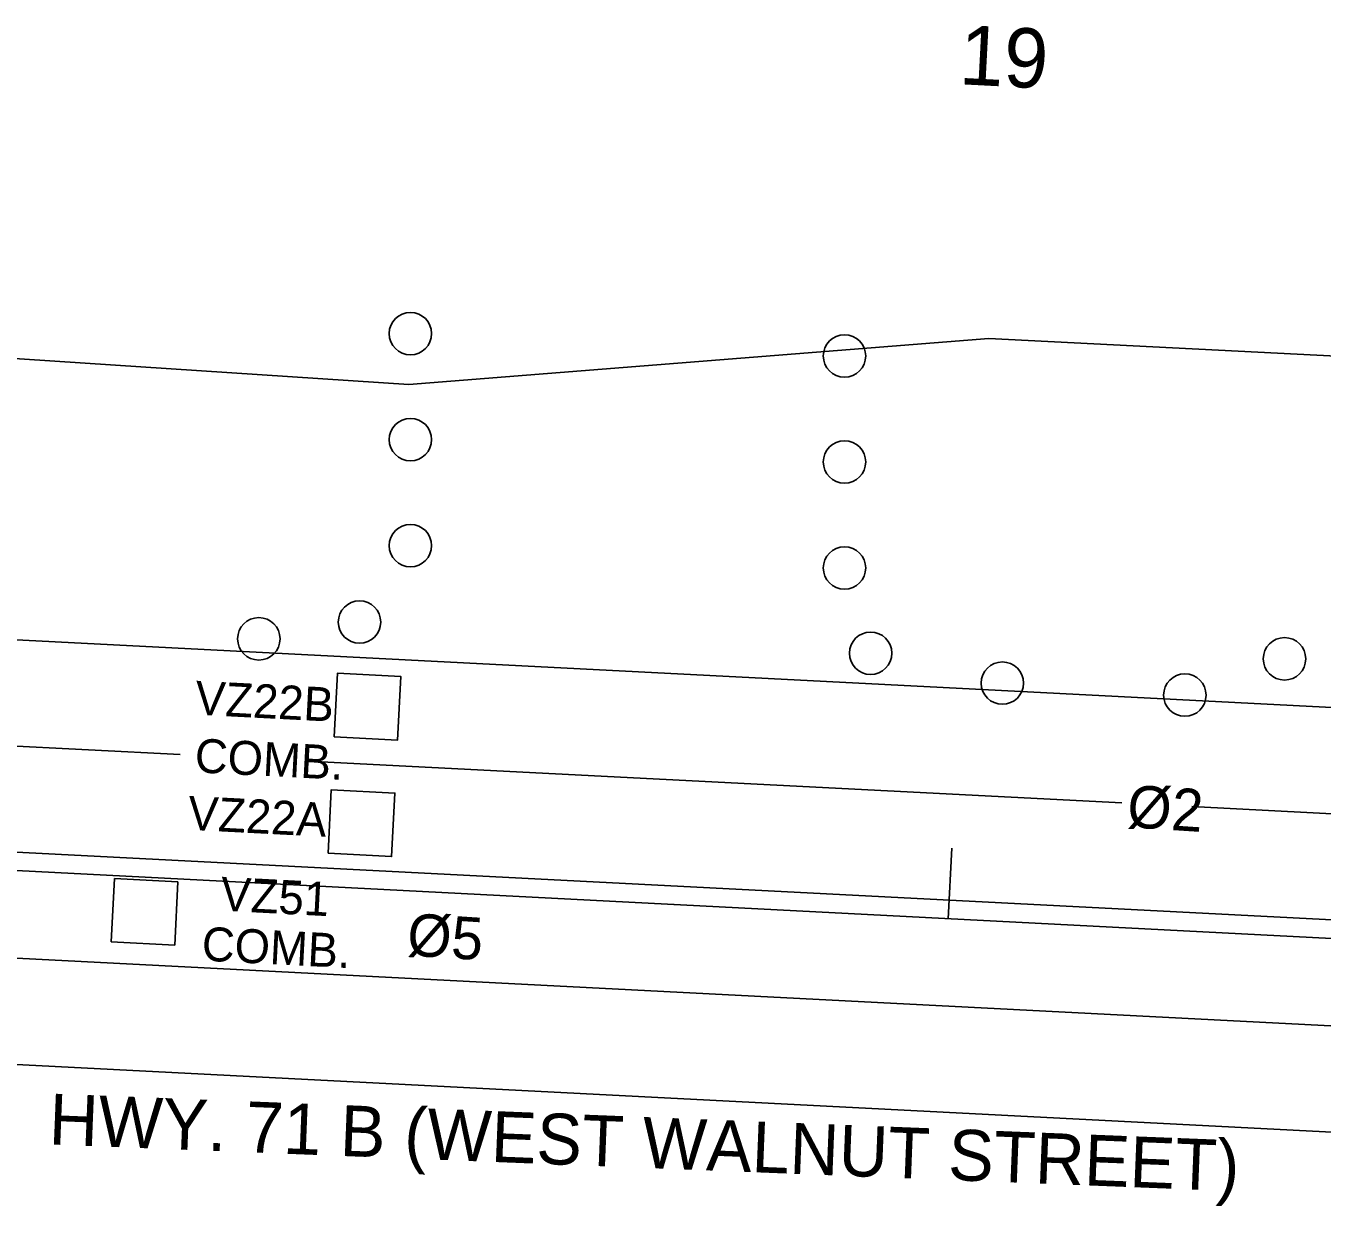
# Model space of a CAD drawing. Extents: x 679444 to 687671, y 733868 to 736107.
# Drawn here: x 681092.3 to 681214.5, y 735100.5 to 735212.9 of the extents above; entities that cross this region are included whole.
import ezdxf

# ---------------------------------------------------------------- set-up
doc = ezdxf.new("R2010")
doc.units = 0
for name, color, linetype in [('$', 7, 'Continuous'), ('MOT Stage 1', 7, 'Continuous'), ('MOT Stage 1 Lanes', 7, 'Continuous'), ('R_Horz Alg Station', 7, 'Continuous'), ('RW-EX', 7, 'Continuous'), ('TITEXT', 7, 'Continuous'), ('Video-Zones-pr', 7, 'Continuous')]:
    doc.layers.add(name, color=color, linetype=linetype)

# ---------------------------------------------------------------- blocks, each defined once
blk = doc.blocks.new('BAREL_1498')
at = {"layer": 'MOT Stage 1'}
blk.add_circle((0, 0.01), 2.88, dxfattribs=at)
blk = doc.blocks.new('BAREL_1499')
at = {"layer": 'MOT Stage 1'}
blk.add_circle((0, 0.01), 2.88, dxfattribs=at)
blk = doc.blocks.new('BAREL_1500')
at = {"layer": 'MOT Stage 1'}
blk.add_circle((0, 0.01), 2.88, dxfattribs=at)
blk = doc.blocks.new('BAREL_1501')
at = {"layer": 'MOT Stage 1'}
blk.add_circle((0, 0.01), 2.88, dxfattribs=at)
blk = doc.blocks.new('BAREL_1502')
at = {"layer": 'MOT Stage 1'}
blk.add_circle((0, 0.01), 2.88, dxfattribs=at)
blk = doc.blocks.new('BAREL_1504')
at = {"layer": 'MOT Stage 1'}
blk.add_circle((0, 0.01), 2.88, dxfattribs=at)
blk = doc.blocks.new('BAREL_1505')
at = {"layer": 'MOT Stage 1'}
blk.add_circle((0, 0.01), 2.88, dxfattribs=at)
blk = doc.blocks.new('BAREL_1506')
at = {"layer": 'MOT Stage 1'}
blk.add_circle((0, 0.01), 2.88, dxfattribs=at)
blk = doc.blocks.new('BAREL_1507')
at = {"layer": 'MOT Stage 1'}
blk.add_circle((0, 0.01), 2.88, dxfattribs=at)
blk = doc.blocks.new('BAREL_1525')
at = {"layer": 'MOT Stage 1'}
blk.add_circle((0, 0.01), 2.88, dxfattribs=at)
blk = doc.blocks.new('BAREL_1541')
at = {"layer": 'MOT Stage 1'}
blk.add_circle((0, 0.01), 2.88, dxfattribs=at)
blk = doc.blocks.new('BAREL_1542')
at = {"layer": 'MOT Stage 1'}
blk.add_circle((0, 0.01), 2.88, dxfattribs=at)

msp = doc.modelspace()

# ---------------------------------------------------------------- linework, layer by layer
at = {"layer": 'MOT Stage 1 Lanes'}
for p, q in [((681043.86, 735157.43), (681230.33, 735147.83)), ((681043.34, 735147.44), (681106.86, 735144.17)), ((681120.16, 735143.49), (681195.65, 735139.6)), ((681202.27, 735139.26), (681229.82, 735137.84)), ((681042.83, 735137.46), (681229.3, 735127.86)), ((681041.8, 735117.48), (681228.28, 735107.88))]:
    msp.add_line(p, q, dxfattribs=at)
msp.add_lwpolyline([(681042.86, 735157.48), (681041.31, 735127.52), (681228.79, 735117.87)], dxfattribs=at)
at = {"layer": 'R_Horz Alg Station'}
msp.add_line((680979.55, 735139), (682304.99, 735070.5), dxfattribs=at)
msp.add_lwpolyline([(681179.63, 735135.34), (681179.28, 735128.68)], dxfattribs=at)
at = {"layer": 'RW-EX'}
msp.add_lwpolyline([(681053.04, 735199.88), (681077.83, 735182.39), (681128.41, 735179.07), (681183.11, 735183.4), (681262.95, 735179.36), (681262.33, 735164.44), (681417.02, 735156.45)], dxfattribs=at)
at = {"layer": 'Video-Zones-pr'}
for points in [[(681121.36, 735145.84), (681121.67, 735151.83), (681127.66, 735151.52), (681127.35, 735145.53)], [(681120.79, 735134.85), (681121.1, 735140.84), (681127.1, 735140.53), (681126.79, 735134.54)]]:
    msp.add_lwpolyline(points, close=True, dxfattribs=at)
for points in [[(681100.64, 735132.48), (681100.33, 735126.49)], [(681100.64, 735132.48), (681106.64, 735132.17)], [(681106.64, 735132.17), (681106.33, 735126.18)], [(681100.33, 735126.49), (681106.33, 735126.18)]]:
    msp.add_lwpolyline(points, dxfattribs=at)

# ---------------------------------------------------------------- block references
at = {"layer": 'MOT Stage 1', "xscale": 0.6945420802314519, "yscale": 0.6945420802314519, "rotation": 87.04179557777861}
for name, p in [('BAREL_1498', (681128.57, 735183.87)), ('BAREL_1504', (681169.51, 735181.76)), ('BAREL_1499', (681128.57, 735173.87)), ('BAREL_1505', (681169.51, 735171.76)), ('BAREL_1500', (681128.57, 735163.87)), ('BAREL_1506', (681169.51, 735161.76)), ('BAREL_1501', (681123.77, 735156.66)), ('BAREL_1502', (681114.27, 735155.08)), ('BAREL_1507', (681171.97, 735153.72)), ('BAREL_1541', (681211.01, 735153.19)), ('BAREL_1525', (681184.4, 735150.9)), ('BAREL_1542', (681201.61, 735149.77))]:
    msp.add_blockref(name, p, dxfattribs=at)

# ---------------------------------------------------------------- texts
at = {"layer": '$'}
for s, height, rotation, p in [('19', 5.6, 357.0415, (681180.25, 735207.4)), ('VZ22B', 3.2, 357.065, (681108.2, 735147.93)), ('COMB.', 3.2, 357.065, (681108.17, 735142.49)), ('VZ22A', 3.2, 357.065, (681107.52, 735137.07)), ('VZ51', 3.2, 357.065, (681110.6, 735129.44)), ('COMB.', 3.2, 357.065, (681108.83, 735124.73)), ('HWY. 71 B (WEST WALNUT STREET)', 4.8, 357.7394, (681094.41, 735107.39))]:
    msp.add_text(s, height=height, rotation=rotation, dxfattribs=at).set_placement(p)
at = {"layer": 'TITEXT'}
for s, p in [('%%C2', (681196.08, 735137.32)), ('%%C5', (681128.17, 735125.22))]:
    msp.add_text(s, height=4, rotation=356.2723, dxfattribs=at).set_placement(p)

doc.saveas('drawing.dxf')
